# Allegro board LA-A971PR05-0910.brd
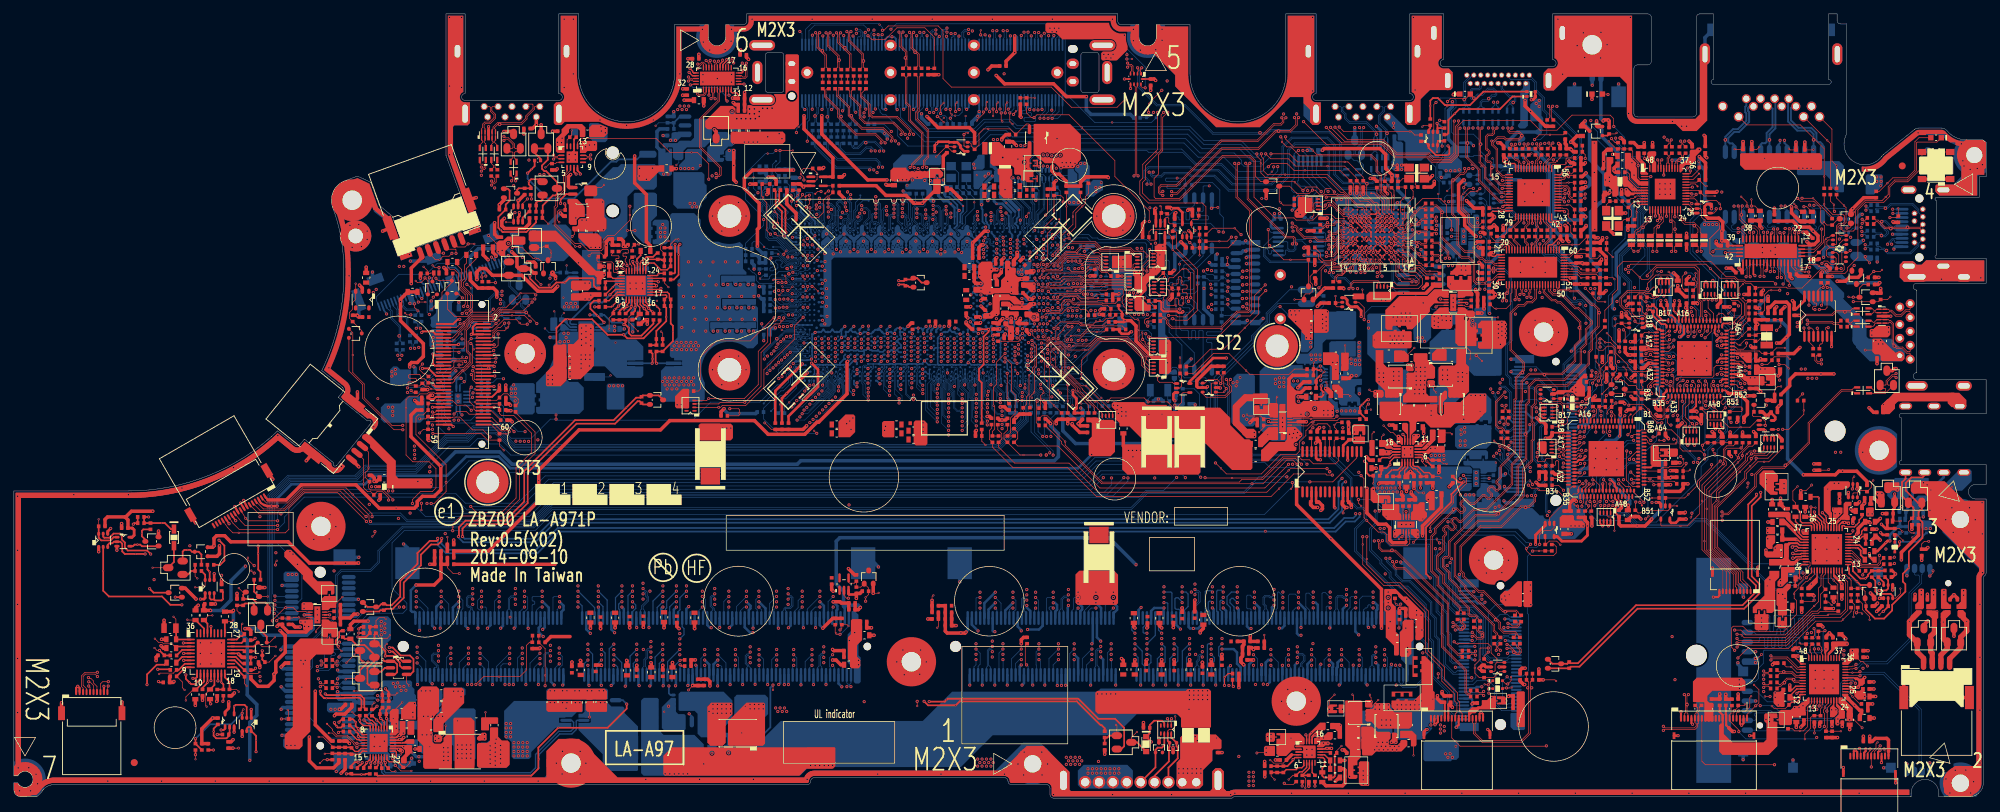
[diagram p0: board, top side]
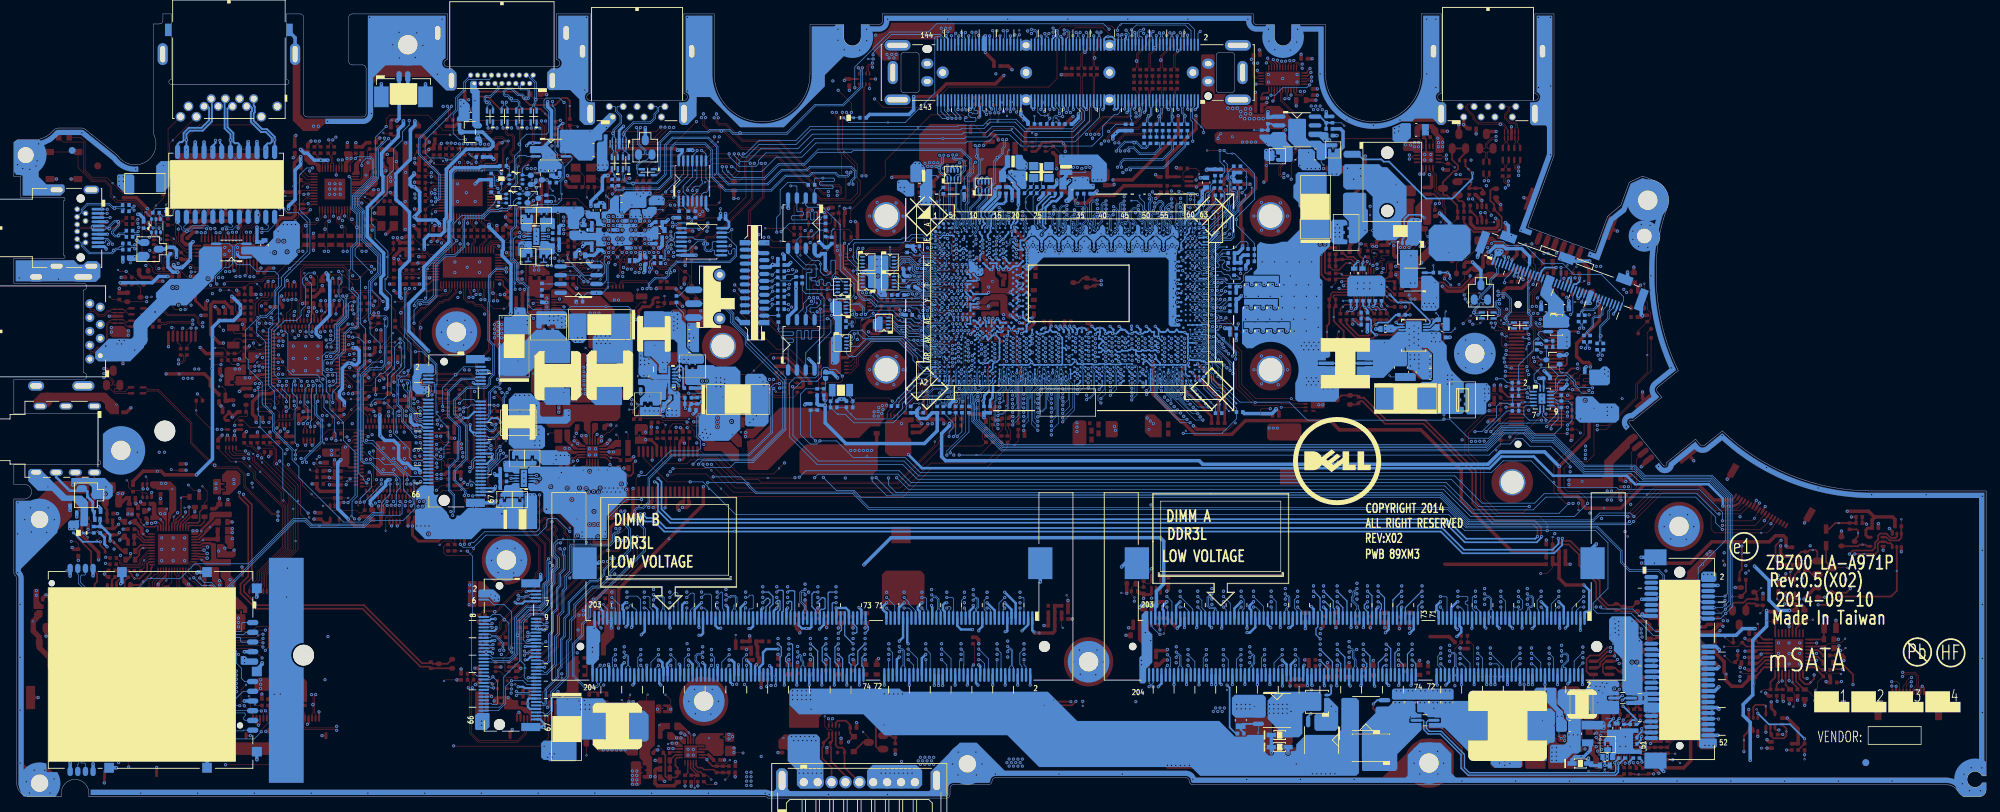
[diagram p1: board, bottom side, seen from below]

Outline 283.9 x 113 mm; copper layers: TOP, GND1, IN1, GND2, IN2, IN3, VCC, IN4, GND3, BOTTOM. Coordinates in mm from the lower left corner of the outline.

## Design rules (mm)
net group 18: nets H_THERMTRIP# H_THERMTRIP#_R
net group CPU_DPB_AUX_C: nets CPU_DPB_AUX#_C CPU_DPB_AUX_C
net group CPU_DPB_CTRL: nets CPU_DPB_CTRLCLK CPU_DPB_CTRLDAT
net group CPU_DPC_CTRL: nets CPU_DPC_CTRLCLK CPU_DPC_CTRLDAT
net group CRT-SYNC: nets HSYNC_DOCK VSYNC_DOCK
net group DDR_A_DQS0: nets DDR_A_DQS0 DDR_A_DQS#0
net group DDR_A_DQS2: nets DDR_A_DQS2 DDR_A_DQS#2
net group DDR_A_DQS4: nets DDR_A_DQS4 DDR_A_DQS#4
net group DDR_A_DQS6: nets DDR_A_DQS6 DDR_A_DQS#6
net group DDR_B_DQS0: nets DDR_B_DQS0 DDR_B_DQS#0
net group DDR_B_DQS2: nets DDR_B_DQS2 DDR_B_DQS#2
net group DDR_B_DQS4: nets DDR_B_DQS4 DDR_B_DQS#4
net group DDR_B_DQS6: nets DDR_B_DQS6 DDR_B_DQS#6
net group DDRA_CLK: nets M_CLK_DDR1 M_CLK_DDR#1
net group DDRB_CLK: nets M_CLK_DDR2 M_CLK_DDR#2
net group DIFFPAIR2: nets SW_MDP_AUX#_C SW_MDP_AUX_C
net group DP: nets CPU_DPB_AUX CPU_DPB_AUX#
net group M_CLK_DDR0: nets M_CLK_DDR0 M_CLK_DDR#0
net group M_CLK_DDR3: nets M_CLK_DDR3 M_CLK_DDR#3
net group REM_DIODE2_: nets REM_DIODE2_N REM_DIODE2_P
net group USB2.0: nets PS_USBP0_D+ PS_USBP0_D-
net group VMM_DPB_CTRL: nets VMM_DPB_CTRLCLK VMM_DPB_CTRLDAT
net group VMM_DPC_CTRL: nets VMM_DPC_CTRLCLK VMM_DPC_CTRLDAT
net group 10: nets INT_SPK_L+ INT_SPK_L- INT_SPK_R+ INT_SPK_R- INT_SPKR_L+ INT_SPKR_L- INT_SPKR_R+ INT_SPKR_R- VCCSENSE VSSSENSE
net group 12: nets H_CATERR# H_CPUPWRGD H_PROCHOT# H_PROCHOT#_R PCH_JTAG_TCK PCH_JTAG_TDI PCH_JTAG_TDO PCH_JTAG_TMS PCH_PLTRST# PCH_PLTRST#_EC PLTRST_LAN# PLTRST_MMI# PLTRST_USH# THERMATRIP2# THERMATRIP3# XDP_RST#_R
net group 12/12/15: nets BC_CLK_ECE1117 BC_CLK_ECE5048 BC_DAT_ECE1117 BC_DAT_ECE5048
net group 15: nets CHARGER_SMBCLK CHARGER_SMBDAT CLK_KBD CLK_MSE CLK_TP_SIO DAT_KBD DAT_MSE DAT_TP_SIO DDR_XDP_WAN_SMBCLK DDR_XDP_WAN_SMBDAT DMIC_CLK DMIC_CLK_L DOCK_SMB_CLK DOCK_SMB_DAT GPU_SMBCLK GPU_SMBDAT I2C1_SCL_VMM I2C1_SDA_VMM LAN_SMBCLK LAN_SMBDATA MEM_SMBCLK MEM_SMBDATA PBAT_SMBCLK PBAT_SMBDAT PCH_RTCRST# PCH_RTCX1 PCH_RTCX1_R PCH_RTCX2 SIO_SLP_A# SML0_SMBCLK SML0_SMBDATA SML1_SMBCLK SML1_SMBDATA SPI_CLK32 SPI_DIN32 SPI_DIN64 SPI_DO32 SPI_DO64 SPI_PCH_CS0#_R SPI_PCH_CS1#_R SPI_PCH_DO2_32 SPI_PCH_DO2_64 SPI_PCH_DO3_32 SPI_PCH_DO3_64 SRTCRST# SUSCLK SUSCLK_R USH_SMBCLK USH_SMBDAT XDP_DBRESET#
net group 20: nets CLK_PCI_DOCK CLK_PCI_LPDEBUG CLK_PCI_MEC CLK_PCI_SIO DOCK_LOM_TRD0+ DOCK_LOM_TRD0- DOCK_LOM_TRD1+ DOCK_LOM_TRD1- DOCK_LOM_TRD2+ DOCK_LOM_TRD2- DOCK_LOM_TRD3+ DOCK_LOM_TRD3- LAN_TX0+ LAN_TX0+L LAN_TX0- LAN_TX0-L LAN_TX1+ LAN_TX1+L LAN_TX1- LAN_TX1-L LAN_TX2+ LAN_TX2+L LAN_TX2- LAN_TX2-L LAN_TX3+ LAN_TX3+L LAN_TX3- LAN_TX3-L NB_LAN_TX0+ NB_LAN_TX0- NB_LAN_TX1+ NB_LAN_TX1- NB_LAN_TX2+ NB_LAN_TX2- NB_LAN_TX3+ NB_LAN_TX3- SPI_CLK64 SW_LAN_TX0+ SW_LAN_TX0- SW_LAN_TX1+ SW_LAN_TX1- SW_LAN_TX2+ SW_LAN_TX2- SW_LAN_TX3+ SW_LAN_TX3-
net group 20/15: nets CLK_PCIE_LAN CLK_PCIE_LAN# CLK_PCIE_MMI CLK_PCIE_MMI# CLK_PCIE_SATA CLK_PCIE_SATA# CLK_PCIE_WIGIG CLK_PCIE_WIGIG# CLK_PCIE_WLAN CLK_PCIE_WLAN# CPU_DPC_AUX CPU_DPC_AUX# DDI2_LANE_N0 DDI2_LANE_N1 DDI2_LANE_N2 DDI2_LANE_N3 DDI2_LANE_P0 DDI2_LANE_P1 DDI2_LANE_P2 DDI2_LANE_P3 DOCK_USBP0+ DOCK_USBP0- DOCK_USBP3+ DOCK_USBP3- DPB_DOCK_AUX DPB_DOCK_AUX# DPB_DOCK_LANE_N0 DPB_DOCK_LANE_N1 DPB_DOCK_LANE_N2 DPB_DOCK_LANE_N3 DPB_DOCK_LANE_P0 DPB_DOCK_LANE_P1 DPB_DOCK_LANE_P2 DPB_DOCK_LANE_P3 DPB_LANE_N0 DPB_LANE_N0_C DPB_LANE_N1 DPB_LANE_N1_C DPB_LANE_N2 DPB_LANE_N2_C DPB_LANE_N3 DPB_LANE_N3_C DPB_LANE_P0 DPB_LANE_P0_C DPB_LANE_P1 DPB_LANE_P1_C DPB_LANE_P2 DPB_LANE_P2_C DPB_LANE_P3 DPB_LANE_P3_C DPC_DOCK_AUX DPC_DOCK_AUX# DPC_DOCK_LANE_N0 DPC_DOCK_LANE_N1 DPC_DOCK_LANE_N2 DPC_DOCK_LANE_N3 DPC_DOCK_LANE_P0 DPC_DOCK_LANE_P1 DPC_DOCK_LANE_P2 DPC_DOCK_LANE_P3 DPC_LANE_N0 DPC_LANE_N0_C DPC_LANE_N1 DPC_LANE_N1_C DPC_LANE_N2 DPC_LANE_N2_C DPC_LANE_N3 DPC_LANE_N3_C DPC_LANE_P0 DPC_LANE_P0_C DPC_LANE_P1 DPC_LANE_P1_C DPC_LANE_P2 DPC_LANE_P2_C DPC_LANE_P3 DPC_LANE_P3_C EDP_CPU_AUX EDP_CPU_AUX# EDP_CPU_AUX#_C EDP_CPU_AUX_C EDP_CPU_LANE_N0 EDP_CPU_LANE_N0_C EDP_CPU_LANE_N1 EDP_CPU_LANE_N1_C EDP_CPU_LANE_P0 EDP_CPU_LANE_P0_C EDP_CPU_LANE_P1 EDP_CPU_LANE_P1_C HDMI_LANE_N0 HDMI_LANE_N1 HDMI_LANE_N2 HDMI_LANE_N3 HDMI_LANE_P0 HDMI_LANE_P1 HDMI_LANE_P2 HDMI_LANE_P3 MDP_AUX#_C MDP_AUX_C MDP_LANE_N0_C MDP_LANE_N1_C MDP_LANE_N2_C MDP_LANE_N3_C MDP_LANE_P0_C MDP_LANE_P1_C MDP_LANE_P2_C MDP_LANE_P3_C PCIE_PRX_GLANTX_N3 PCIE_PRX_GLANTX_N3_C PCIE_PRX_GLANTX_P3 PCIE_PRX_GLANTX_P3_C PCIE_PRX_MMITX_N1 PCIE_PRX_MMITX_N1_C PCIE_PRX_MMITX_P1 PCIE_PRX_MMITX_P1_C PCIE_PRX_SATATX_N6_L0 PCIE_PRX_SATATX_N6_L1 PCIE_PRX_SATATX_P6_L0 PCIE_PRX_SATATX_P6_L1 PCIE_PRX_WIGIGTX_N5 PCIE_PRX_WIGIGTX_P5 PCIE_PRX_WLANTX_N4 PCIE_PRX_WLANTX_P4 PCIE_PTX_GLANRX_N3 PCIE_PTX_GLANRX_N3_C PCIE_PTX_GLANRX_P3 PCIE_PTX_GLANRX_P3_C PCIE_PTX_MMIRX_N1 PCIE_PTX_MMIRX_N1_C PCIE_PTX_MMIRX_P1 PCIE_PTX_MMIRX_P1_C PCIE_PTX_SATARX_N6_L0 PCIE_PTX_SATARX_N6_L0_C PCIE_PTX_SATARX_N6_L1 PCIE_PTX_SATARX_N6_L1_C PCIE_PTX_SATARX_P6_L0 PCIE_PTX_SATARX_P6_L0_C PCIE_PTX_SATARX_P6_L1 PCIE_PTX_SATARX_P6_L1_C PCIE_PTX_WIGIGRX_N5 PCIE_PTX_WIGIGRX_N5_C PCIE_PTX_WIGIGRX_P5 PCIE_PTX_WIGIGRX_P5_C PCIE_PTX_WLANRX_N4 PCIE_PTX_WLANRX_N4_C PCIE_PTX_WLANRX_P4 PCIE_PTX_WLANRX_P4_C PS8338_AUX PS8338_AUX# PS8338_N0 PS8338_N0_C PS8338_N1 PS8338_N1_C PS8338_N2 PS8338_N2_C PS8338_N3 PS8338_N3_C PS8338_P0 PS8338_P0_C PS8338_P1 PS8338_P1_C PS8338_P2 PS8338_P2_C PS8338_P3 PS8338_P3_C SATA_PRX_DKTX_N0 SATA_PRX_DKTX_N0_C SATA_PRX_DKTX_P0 SATA_PRX_DKTX_P0_C SATA_PRX_DTX_N1 SATA_PRX_DTX_N1_C SATA_PRX_DTX_P1 SATA_PRX_DTX_P1_C SATA_PTX_DKRX_N0 SATA_PTX_DKRX_N0_C SATA_PTX_DKRX_P0 SATA_PTX_DKRX_P0_C SATA_PTX_DRX_N1 SATA_PTX_DRX_N1_C SATA_PTX_DRX_P1 SATA_PTX_DRX_P1_C SW_DPB_AUX SW_DPB_AUX# SW_DPB_AUX#_C SW_DPB_AUX_C SW_DPC_AUX SW_DPC_AUX# SW_DPC_AUX#_C SW_DPC_AUX_C SW_USBP3+ SW_USBP3- TMDS_CON_N0 TMDS_CON_N1 TMDS_CON_N2 TMDS_CON_P0 TMDS_CON_P1 TMDS_CON_P2 USB3RN1 USB3RN1_D- USB3RN2 USB3RN2_D- USB3RN4 USB3RN4_D- USB3RP1 USB3RP1_D+ USB3RP2 USB3RP2_D+ USB3RP4 USB3RP4_D+ USB3TN1 USB3TN1_D- USB3TN2 USB3TN2_C USB3TN2_D- USB3TN4 USB3TN4_C USB3TN4_D- USB3TP1 USB3TP1_D+ USB3TP2 USB3TP2_C USB3TP2_D+ USB3TP4 USB3TP4_C USB3TP4_D+ USBP0+ USBP0- USBP1+ USBP1- USBP1_R_D+ USBP1_R_D- USBP2+ USBP2- USBP3+ USBP3- USBP3_D+ USBP3_D- USBP4+ USBP4- USBP4_D+ USBP4_D- USBP5+ USBP5- USBP5_D+ USBP5_D- USBP6+ USBP6- USBP7+ USBP7- USBRBIAS VMM2320_AUX VMM2320_AUX# VMM2320_AUX#_C VMM2320_AUX_C VMM2320_N0 VMM2320_N0_C VMM2320_N1 VMM2320_N1_C VMM2320_N2 VMM2320_N2_C VMM2320_N3 VMM2320_N3_C VMM2320_P0 VMM2320_P0_C VMM2320_P1 VMM2320_P1_C VMM2320_P2 VMM2320_P2_C VMM2320_P3 VMM2320_P3_C WIGIG_AUX WIGIG_AUX# WIGIG_AUX#_C WIGIG_AUX_C WIGIG_LANE_N0 WIGIG_LANE_N0_C WIGIG_LANE_N1 WIGIG_LANE_N1_C WIGIG_LANE_N2 WIGIG_LANE_N2_C WIGIG_LANE_N3 WIGIG_LANE_N3_C WIGIG_LANE_P0 WIGIG_LANE_P0_C WIGIG_LANE_P1 WIGIG_LANE_P1_C WIGIG_LANE_P2 WIGIG_LANE_P2_C WIGIG_LANE_P3 WIGIG_LANE_P3_C
net group 24/20/18: nets SD_UHS2_D0N SD_UHS2_D0P SD_UHS2_D1N SD_UHS2_D1P
net group CRT-DAC: nets BLUE_DOCK GREEN_DOCK RED_DOCK
net group DDI1: nets DDI1_LANE_N0 DDI1_LANE_N0_C DDI1_LANE_N1 DDI1_LANE_N1_C DDI1_LANE_N2 DDI1_LANE_N2_C DDI1_LANE_N3 DDI1_LANE_N3_C DDI1_LANE_P0 DDI1_LANE_P0_C DDI1_LANE_P1 DDI1_LANE_P1_C DDI1_LANE_P2 DDI1_LANE_P2_C DDI1_LANE_P3 DDI1_LANE_P3_C
net group DDRA_CMD: nets DDR_A_BS0 DDR_A_BS1 DDR_A_BS2 DDR_A_CAS# DDR_A_MA0 DDR_A_MA1 DDR_A_MA2 DDR_A_MA3 DDR_A_MA4 DDR_A_MA5 DDR_A_MA6 DDR_A_MA7 DDR_A_MA8 DDR_A_MA9 DDR_A_MA10 DDR_A_MA11 DDR_A_MA12 DDR_A_MA13 DDR_A_MA14 DDR_A_MA15 DDR_A_RAS# DDR_A_WE#
net group DDRA_CTL: nets DDR_CKE0_DIMMA DDR_CKE1_DIMMA DDR_CS0_DIMMA# DDR_CS1_DIMMA# M_ODT0 M_ODT1
net group DDRA_D0: nets DDR_A_D0 DDR_A_D1 DDR_A_D2 DDR_A_D3 DDR_A_D4 DDR_A_D5 DDR_A_D6 DDR_A_D7
net group DDRA_D1: nets DDR_A_D8 DDR_A_D9 DDR_A_D10 DDR_A_D11 DDR_A_D12 DDR_A_D13 DDR_A_D14 DDR_A_D15
net group DDRA_D2: nets DDR_A_D16 DDR_A_D17 DDR_A_D18 DDR_A_D19 DDR_A_D20 DDR_A_D21 DDR_A_D22 DDR_A_D23
net group DDRA_D3: nets DDR_A_D24 DDR_A_D25 DDR_A_D26 DDR_A_D27 DDR_A_D28 DDR_A_D29 DDR_A_D30 DDR_A_D31
net group DDRA_D4: nets DDR_A_D32 DDR_A_D33 DDR_A_D34 DDR_A_D35 DDR_A_D36 DDR_A_D37 DDR_A_D38 DDR_A_D39
net group DDRA_D5: nets DDR_A_D40 DDR_A_D41 DDR_A_D42 DDR_A_D43 DDR_A_D44 DDR_A_D45 DDR_A_D46 DDR_A_D47
net group DDRA_D6: nets DDR_A_D48 DDR_A_D49 DDR_A_D50 DDR_A_D51 DDR_A_D52 DDR_A_D53 DDR_A_D54 DDR_A_D55
net group DDRA_D7: nets DDR_A_D56 DDR_A_D57 DDR_A_D58 DDR_A_D59 DDR_A_D60 DDR_A_D61 DDR_A_D62 DDR_A_D63
net group DDRA_DQS: nets DDR_A_DQS1 DDR_A_DQS3 DDR_A_DQS5 DDR_A_DQS7 DDR_A_DQS#1 DDR_A_DQS#3 DDR_A_DQS#5 DDR_A_DQS#7
net group DDRB_CMD: nets DDR_B_BS0 DDR_B_BS1 DDR_B_BS2 DDR_B_CAS# DDR_B_MA0 DDR_B_MA1 DDR_B_MA2 DDR_B_MA3 DDR_B_MA4 DDR_B_MA5 DDR_B_MA6 DDR_B_MA7 DDR_B_MA8 DDR_B_MA9 DDR_B_MA10 DDR_B_MA11 DDR_B_MA12 DDR_B_MA13 DDR_B_MA14 DDR_B_MA15 DDR_B_RAS# DDR_B_WE#
net group DDRB_CTL: nets DDR_CKE2_DIMMB DDR_CKE3_DIMMB DDR_CS2_DIMMB# DDR_CS3_DIMMB# M_ODT2 M_ODT3
net group DDRB_D0: nets DDR_B_D0 DDR_B_D1 DDR_B_D2 DDR_B_D3 DDR_B_D4 DDR_B_D5 DDR_B_D6 DDR_B_D7
net group DDRB_D1: nets DDR_B_D8 DDR_B_D9 DDR_B_D10 DDR_B_D11 DDR_B_D12 DDR_B_D13 DDR_B_D14 DDR_B_D15
net group DDRB_D2: nets DDR_B_D16 DDR_B_D17 DDR_B_D18 DDR_B_D19 DDR_B_D20 DDR_B_D21 DDR_B_D22 DDR_B_D23
net group DDRB_D3: nets DDR_B_D24 DDR_B_D25 DDR_B_D26 DDR_B_D27 DDR_B_D28 DDR_B_D29 DDR_B_D30 DDR_B_D31
net group DDRB_D4: nets DDR_B_D32 DDR_B_D33 DDR_B_D34 DDR_B_D35 DDR_B_D36 DDR_B_D37 DDR_B_D38 DDR_B_D39
net group DDRB_D5: nets DDR_B_D40 DDR_B_D41 DDR_B_D42 DDR_B_D43 DDR_B_D44 DDR_B_D45 DDR_B_D46 DDR_B_D47
net group DDRB_D6: nets DDR_B_D48 DDR_B_D49 DDR_B_D50 DDR_B_D51 DDR_B_D52 DDR_B_D53 DDR_B_D54 DDR_B_D55
net group DDRB_D7: nets DDR_B_D56 DDR_B_D57 DDR_B_D58 DDR_B_D59 DDR_B_D60 DDR_B_D61 DDR_B_D62 DDR_B_D63
net group DDRB_DQS: nets DDR_B_DQS1 DDR_B_DQS3 DDR_B_DQS5 DDR_B_DQS7 DDR_B_DQS#1 DDR_B_DQS#3 DDR_B_DQS#5 DDR_B_DQS#7
net group DMIC: nets DMIC0
net group HDA_8_15: nets PCH_AZ_BITCLK PCH_AZ_CODEC_BITCLK PCH_AZ_CODEC_RST# PCH_AZ_CODEC_SDIN0 PCH_AZ_CODEC_SDOUT PCH_AZ_CODEC_SYNC PCH_AZ_RST# PCH_AZ_SDIN0_R PCH_AZ_SDOUT PCH_AZ_SYNC
net group HDMI: nets HDMI_CLK_AUX HDMI_DAT_AUX# TMDS_CON_CLK TMDS_CON_CLK#
net group SD-CARD: nets SD/MMCCD# SD/MMCCLK SD/MMCCLK_R SD/MMCCMD SD/MMCDAT0 SD/MMCDAT1 SD/MMCDAT2 SD/MMCDAT2_R SD/MMCDAT3 SD/MMCDAT3_R SD_REXT SDWP
net group SPI: nets PCH_SPI_CLK PCH_SPI_CS0# PCH_SPI_CS1# PCH_SPI_DIN PCH_SPI_DO PCH_SPI_DO2 PCH_SPI_DO3 SPI_PCH_CLK SPI_PCH_CS0# SPI_PCH_CS1# SPI_PCH_DIN SPI_PCH_DO SPI_PCH_DO2 SPI_PCH_DO3
net group SVID: nets VIDALERT_N VIDSCLK VIDSOUT
net group THERMAL: nets REM_DIODE1_N REM_DIODE1_P REM_DIODE4_N REM_DIODE4_P
net group USB3.0: nets DOCK_USB3RN1 DOCK_USB3RP1 DOCK_USB3TN1 DOCK_USB3TP1 SW_USB3RN1 SW_USB3RP1 SW_USB3TN1 SW_USB3TP1 SW_USBP0+ SW_USBP0- USB3TN1_C USB3TP1_C USBP0_R_D+ USBP0_R_D-
nets with their own width: min track width 0.254; nets +3.3V_WWAN AUD_SENSE_A AUD_SENSE_B BAT1_LED# BAT1_LED#_Q BAT2_LED# BAT2_LED#_Q BATT_WHITE# BATT_YELLOW# CLK_BIASREF
nets with their own width: min track width 0.381; nets +PCH_RTC_VCCSUS3_3 +PCH_VCCDSW3_3 AUD_HP_OUT_L AUD_HP_OUT_L1 AUD_HP_OUT_R AUD_HP_OUT_R1 AUD_OUT_L AUD_OUT_R CFG_RCOMP PCH_OPI_COMP PCH_PCIE_RCOMP PROC_OPI_RCOMP SATA_COMP SM_RCOMP0 SM_RCOMP1 SM_RCOMP2 TDI_IREF
nets with their own width: min track width 0.508; nets +1.2V_LDO +1.05V_M +1.05V_MODPHY +1.05V_MODPHY_PCH +1.05V_MP +1.05V_RUN +1.5V_RUN_AUDIO +1.05V_RUN_UZ7 +1.05V_VCCST +1.05V_VMM_UV10 +1.05V_VMM_VDD +1.05V_VMM_VDDTX +1.8V_RUN_CARD +1.35V_MEM +1.35V_MEN_P +3.3V_ALW +3.3V_ALW2 +3.3V_ALW_PCH +3.3V_ALW_UE1 +3.3V_ALW_UE2 +3.3V_ALWP +3.3V_CAM +3.3V_LAN +3.3V_M +3.3V_M_TPM +3.3V_RTC_LDO +3.3V_RUN +3.3V_RUN_AUDIO +3.3V_RUN_UZ9 +3.3V_RUN_VDDA +3.3V_RUN_VDDIO +3.3V_SPI +3.3V_SUS +3.3V_TP +3.3V_VMM_UV10 +5V_ALW +5V_ALW2 +5V_ALWP +5V_RUN +5V_RUN_AUDIO +5V_RUN_UZ9 +AUX_LDO +CAP_LDO +COINCELL +DC_IN +DC_IN_SS +DCIN +DCIN_JACK +DCPRRTC +DIMM1_VREF_DQ +DIMM2_VREF_DQ +DOCK_PWR_BAR +GND_CHASSIS +LOM_VCT +MIC1_VREF_OUT +NBDOCK_DC_IN_SS +PBATT +PCH_ASATA3PLL +PCH_AUSB3PLL +PCH_VCC1P05 +PCH_VCCACLKPLL +PCH_VCCDSW +PCH_VCCDSW_R +RTC_CELL +RTC_CELL_VBAT +SIM_PWR +SM_VREF_CA +SM_VREF_CA_DIMM +SM_VREF_DQ0 +SM_VREF_DQ1 +V_DDR_REF +VCC_CORE +VCCIO_OUT +VCCIOA_OUT +VDDA_AVDD1 +VDDA_PVDD +VLDOIN_1.35V +VR_CAP +VREFOUT EDP_COMP GND GNDA N33048 N33050 N5261056
nets with their own width: min track width 1.016; nets +0.9V_LAN +1.5V_RUN +1.05V_RUN_VMM +3.3V_RUN_CARD +3.3V_RUN_VMM +3.3V_TSP +BL_PWR_SRC +VDISPLAY_VCC +VHDMI_VCC REGCTL_PNP10
nets with their own width: min track width 1.27; nets RING2 SLEEVE
nets with their own width: min track width 1.524; nets +0.675V_DDR_VTT +0.675V_P +3.3V_MMI +PWR_SRC
nets with their own width: min track width 2.032; nets +3.3V_HDD +3.3V_WLAN +5V_USB_CHG_PWR +LCDVDD +USB_RIGHT_PWR +USB_SIDE_PWR

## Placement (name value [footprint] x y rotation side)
C33  4.7U_0805_25V6-K  [C_0805]  106.62 97.01 270 top
C42  4.7P_0402_50V8C  [C_0402]  132.59 97.14 180 bottom
C43  4.7P_0402_50V8C  [C_0402]  137 97.14 0 bottom
C263  0.1U_0402_16V4Z  [C_0402]  267.14 8.17 180 top
C294  0.1U_0402_10V7K  [C_0402]  116.44 102.21 90 top
C295  0.1U_0402_10V7K  [C_0402]  115.86 95.25 270 bottom
C296  0.1U_0402_10V7K  [C_0402]  117.32 102.21 90 top
C297  0.1U_0402_10V7K  [C_0402]  116.75 95.25 270 bottom
C298  0.1U_0402_10V7K  [C_0402]  118.21 102.21 90 top
C299  0.1U_0402_10V7K  [C_0402]  117.64 95.25 270 bottom
C300  0.1U_0402_10V7K  [C_0402]  120.31 95.25 270 bottom
C301  0.1U_0402_10V7K  [C_0402]  121.2 95.25 270 bottom
C302  0.1U_0402_10V7K  [C_0402]  114.97 95.25 270 bottom
C303  0.1U_0402_10V7K  [C_0402]  119.1 102.21 90 top
C304  0.1U_0402_10V7K  [C_0402]  118.53 95.25 270 bottom
C305  0.1U_0402_10V7K  [C_0402]  119.99 102.21 90 top
C306  0.1U_0402_10V7K  [C_0402]  119.42 95.25 270 bottom
C307  0.1U_0402_10V7K  [C_0402]  120.88 102.21 90 top
C308  0.1U_0402_10V7K  [C_0402]  121.77 102.21 90 top
C309  0.1U_0402_10V7K  [C_0402]  122.66 102.21 90 top
C310  0.033U_0402_16V7K  [C_0402]  122.98 97.09 270 bottom
C311  0.033U_0402_16V7K  [C_0402]  131.6 105.16 270 top
C312  0.01U_0402_16V7K  [C_0402]  127.99 104.24 90 top
C313  0.01U_0402_16V7K  [C_0402]  128.88 104.24 90 top
C314  0.01U_0402_16V7K  [C_0402]  129.77 105.16 270 top
C315  0.01U_0402_16V7K  [C_0402]  130.66 105.16 270 top
C316  1U_0402_6.3V6K  [C_0402]  142.83 105.49 180 top
C317  0.1U_0603_50V7K  [C_0603]  103.8 96.89 270 top
C318  0.1U_0603_50V7K  [C_0603]  105.07 96.89 270 top
C319  4.7P_0402_50V8C  [C_0402]  144.87 100.9 270 top
CA1  680P_0402_50V7K  [C_0402]  273.94 41.19 0 bottom
CA2  220P_0402_50V7K  [C_0402]  272.34 41.24 180 bottom
CA3  220P_0402_50V7K  [C_0402]  270.51 41 180 top
CA4  680P_0402_50V7K  [C_0402]  267.32 43.26 180 top
CA5  100P_0402_50V8J  [C_0402]  67.42 74.41 270 top
CA6  100P_0402_50V8J  [C_0402]  68.31 74.41 270 top
CA7  0.1U_0402_25V6  [C_0402]  66.61 75.6 180 top
CA8  0.1U_0402_25V6  [C_0402]  263.94 40.33 0 top
CA9  10U_0603_6.3V6M  [C_0603]  263.73 41.38 0 top
CA10  4.7U_0603_6.3V6K  [C_0603]  254.62 27.72 0 top
CA11  0.1U_0402_25V6  [C_0402]  258.31 30.21 270 top
CA12  680P_0402_50V7K  [C_0402]  275.81 43.1 270 bottom
CA13  680P_0402_50V7K  [C_0402]  269.09 55.59 180 top
CA16  4.7U_0603_6.3V6K  [C_0603]  254.56 37.38 180 top
CA17  0.1U_0402_25V6  [C_0402]  255.38 40.79 90 top
CA18  4.7U_0603_6.3V6K  [C_0603]  254.31 40.93 90 top
CA19  1000P_0402_50V7K  [C_0402]  277.8 28.6 0 top
CA22  1000P_0402_50V7K  [C_0402]  274.52 28.6 180 top
CA23  1000P_0402_50V7K  [C_0402]  276.36 28.6 180 top
CA24  1000P_0402_50V7K  [C_0402]  280.68 28.6 180 top
CA25  10U_0603_6.3V6M  [C_0603]  258.62 43.41 180 top
CA26  1U_0603_10V4Z  [C_0603]  266.5 39.81 0 top
CA27  0.1U_0402_25V6  [C_0402]  264.47 29.3 90 top
CA28  0.1U_0402_25V6  [C_0402]  265.42 29.3 90 top
CA29  1U_0603_10V6K  [C_0603]  256.46 41.95 270 top
CA30  22P_0402_50V8J  [C_0402]  257.35 28.31 270 top
CA31  1U_0603_10V6K  [C_0603]  256.46 31.66 180 top
CA33  15P_0402_50V8J  [C_0402]  260.78 28.24 270 top
CA35  2.2U_0402_6.3V6M  [C_0402]  266.04 41.76 270 top
CA41  0.1U_0402_25V6  [C_0402]  274.18 40.31 270 top
CA43  4.7U_0603_6.3V6K  [C_0603]  266.45 34.35 0 top
CA44  4.7U_0603_6.3V6K  [C_0603]  266.42 35.58 0 top
CA45  0.1U_0402_25V6  [C_0402]  255.96 33.83 270 top
CA46  10U_0603_6.3V6M  [C_0603]  255.13 35.22 180 top
CA47  0.1U_0402_25V6  [C_0402]  255.21 36.3 180 top
CA48  10U_0603_6.3V6M  [C_0603]  254.88 34.14 270 top
CA49  1U_0603_10V6K  [C_0603]  257.86 41.95 270 top
CA50  0.1U_0402_25V6  [C_0402]  263.13 30.21 270 top
CA51  4.7U_0603_6.3V6K  [C_0603]  266.57 37.69 0 top
CA52  4.7U_0603_6.3V6K  [C_0603]  254.56 39.79 180 top
CA53  4.7U_0603_6.3V6K  [C_0603]  261.93 30.33 270 top
CC1  12P_0402_50V8J  [C_0402]  164.05 57.19 180 bottom
CC2  12P_0402_50V8J  [C_0402]  165.42 57.19 0 bottom
CC3  1U_0402_6.3V6K  [C_0402]  169.22 56.82 270 bottom
CC4  1U_0402_6.3V6K  [C_0402]  167.31 58.06 90 bottom
CC5  27P_0402_50V8J  [C_0402]  149.21 55.52 90 bottom
CC6  0.1U_0402_25V6  [C_0402]  167.12 78.45 90 bottom
CC7  0.1U_0402_25V6  [C_0402]  173.93 77.7 180 bottom
CC8  15P_0402_50V8J  [C_0402]  135.74 87.16 0 bottom
CC9  33P_0402_50V8J  [C_0402]  166.74 72.58 0 top
CC10  33P_0402_50V8J  [C_0402]  166.17 79.91 90 bottom
CC11  15P_0402_50V8J  [C_0402]  138.43 88.05 180 bottom
CC12  33P_0402_50V8J  [C_0402]  140.72 54.74 270 top
CC13  33P_0402_50V8J  [C_0402]  141.63 54.72 270 top
CC14  33P_0402_50V8J  [C_0402]  143.01 54.72 270 top
CC15  33P_0402_50V8J  [C_0402]  143.97 54.15 270 top
CC17  0.1U_0402_25V6  [C_0402]  63.69 60.49 180 bottom
CC18  0.1U_0402_25V6  [C_0402]  69.89 58.78 0 top
CC19  0.1U_0402_25V6  [C_0402]  59.63 57.73 180 top
CC20  22P_0402_50V8J  [C_0402]  105.34 77.35 0 bottom
CC21  0.1U_0402_25V6  [C_0402]  69.9 56.81 0 top
CC22  0.1U_0402_25V6  [C_0402]  59.63 56.87 180 top
CC23  22U_0603_6.3V6M  [C_0603]  137.08 73.19 270 top
CC24  100P_0402_50V8J  [C_0402]  117.89 87.29 0 top
CC25  2.2U_0402_6.3V6M  [C_0402]  129.02 54.02 0 top
CC26  2.2U_0402_6.3V6M  [C_0402]  131.75 68.69 0 top
CC27  2.2U_0402_6.3V6M  [C_0402]  129.35 67.53 90 top
CC28  2.2U_0402_6.3V6M  [C_0402]  135.59 68.66 180 top
CC29  10U_0603_6.3V6M  [C_0603]  128.78 52.94 0 top
CC30  10U_0603_6.3V6M  [C_0603]  128.78 51.67 0 top
CC31  10U_0603_6.3V6M  [C_0603]  127.76 53.83 180 top
CC32  10U_0603_6.3V6M  [C_0603]  127.76 52.56 180 top
CC33  10U_0603_6.3V6M  [C_0603]  117.73 53.83 0 top
CC34  10U_0603_6.3V6M  [C_0603]  117.73 52.56 0 top
CC35  0.1U_0402_25V6  [C_0402]  117.89 89.51 0 top
CC36  22U_0603_6.3V6M  [C_0603]  132.91 87.74 0 top
CC37  1U_0402_6.3V6K  [C_0402]  137.08 69.87 90 top
CC39  330U_D3_2.5VY_R6M  [C_D2]  182.89 57.44 180 bottom
CC40  1U_0402_6.3V6K  [C_0402]  145.54 76.8 135 top
CC41  330U_D3_2.5VY_R6M  [C_D3]  169.28 54.55 270 top
CC42  330U_D3_2.5VY_R6M  [C_D3]  164.52 54.55 270 top
CC43  1U_0402_6.3V6K  [C_0402]  146.71 86.78 180 top
CC44  1U_0402_6.3V6K  [C_0402]  146.71 87.67 180 top
CC47  22U_0603_6.3V6M  [C_0603]  139.7 86.91 0 top
CC48  0.1U_0402_10V7K  [C_0402]  143.58 67.62 90 top
CC49  0.1U_0402_10V7K  [C_0402]  142.74 68.37 180 top
CC50  1U_0402_6.3V6K  [C_0402]  143.46 66.24 180 top
CC51  22U_0603_6.3V6M  [C_0603]  139.7 88.12 0 top
CC52  0.1U_0402_10V7K  [C_0402]  145.78 69.81 90 top
CC53  1U_0402_6.3V6K  [C_0402]  145.8 75.81 270 top
CC54  0.1U_0402_10V7K  [C_0402]  145.25 72.81 180 top
CC55  22U_0603_6.3V6M  [C_0603]  143.4 88.18 0 top
CC56  22U_0603_6.3V6M  [C_0603]  143.4 86.91 0 top
CC57  0.1U_0402_10V7K  [C_0402]  139.83 69.37 90 top
CC58  1U_0402_6.3V6K  [C_0402]  138.5 68.42 90 top
CC59  1U_0402_6.3V6K  [C_0402]  142.18 77 0 top
CC60  10U_0603_6.3V6M  [C_0603]  159.71 53.96 270 top
CC61  1U_0402_6.3V6K  [C_0402]  144.32 69.81 90 top
CC62  22U_0603_6.3V6M  [C_0603]  142.61 69.82 90 top
CC63  22U_0603_6.3V6M  [C_0603]  141.4 71.67 90 top
CC64  22U_0603_6.3V6M  [C_0603]  141.49 74.14 180 top
CC65  1U_0402_6.3V6K  [C_0402]  139.33 52.18 180 top
CC66  0.1U_0402_10V7K  [C_0402]  141.25 75.29 180 top
CC67  100U_1206_6.3V6M  [C_1206]  152.21 87.61 0 bottom
CC68  1U_0402_6.3V6K  [C_0402]  139.81 71.97 90 top
CC69  1U_0402_6.3V6K  [C_0402]  145.25 74.02 180 top
CC70  1U_0402_6.3V6K  [C_0402]  138.5 74.16 270 top
CC71  1U_0402_6.3V6K  [C_0402]  143.94 76.95 270 top
CC72  1U_0402_6.3V6K  [C_0402]  140.97 67.58 90 top
CC73  1U_0402_6.3V6K  [C_0402]  144.45 67.59 90 top
CC77  100U_1206_6.3V6M  [C_1206]  132.89 88.56 180 bottom
CC78  1U_0402_6.3V6K  [C_0402]  141.32 77 180 top
CC79  22U_0603_6.3V6M  [C_0603]  138.25 75.24 180 top
CC80  1U_0402_6.3V6K  [C_0402]  145.78 67.46 90 top
CC81  100U_1206_6.3V6M  [C_1206]  141.59 89.57 180 bottom
CC82  1U_0402_6.3V6K  [C_0402]  139.29 87.16 0 bottom
CC83  100P_0402_50V8J  [C_0402]  112.13 87.59 90 top
CC84  22U_0603_6.3V6M  [C_0603]  138.24 76.5 180 top
CC85  22U_0603_6.3V6M  [C_0603]  126.69 89.71 270 top
CC97  0.47U_0402_10V6K  [C_0402]  138 67.56 0 top
CC100  1U_0402_6.3V6K  [C_0402]  156.86 69.63 0 top
CC101  0.1U_0402_16V4Z  [C_0402]  143.26 56.84 270 top
CC102  0.1U_0402_16V4Z  [C_0402]  114.99 90.73 0 top
CC103  0.1U_0402_16V4Z  [C_0402]  170.56 83.92 180 top
CC104  0.1U_0402_16V4Z  [C_0402]  169.63 79.29 180 top
CC105  0.1U_0402_16V4Z  [C_0402]  167.09 82.52 90 top
CC106  0.1U_0402_16V4Z  [C_0402]  163.39 80.83 180 top
CC107  0.1U_0402_16V4Z  [C_0402]  155.11 73.69 180 bottom
CC108  0.1U_0402_25V6  [C_0402]  154.57 69.62 0 bottom
CC109  0.1U_0402_16V4Z  [C_0402]  107.91 55.63 180 bottom
CC110  0.1U_0402_16V4Z  [C_0402]  123.04 29.82 180 top
CC111  0.1U_0402_16V4Z  [C_0402]  69.9 57.71 0 top
CC112  0.1U_0402_16V4Z  [C_0402]  58.79 59.78 270 top
CD1  0.1U_0402_25V6  [C_0402]  61.47 33.7 180 top
CD2  1U_0402_6.3V6K  [C_0402]  95.43 26.22 270 top
CD3  1U_0402_6.3V6K  [C_0402]  90.61 26.22 270 top
CD4  1U_0402_6.3V6K  [C_0402]  88.64 26.15 270 top
CD5  2.2U_0402_6.3V6M  [C_0402]  61.47 34.65 180 top
CD6  0.1U_0402_25V6  [C_0402]  74.62 22.46 270 top
CD7  1U_0402_6.3V6K  [C_0402]  84.45 26.09 270 top
CD8  1U_0402_6.3V6K  [C_0402]  93.4 17.55 90 top
CD9  1U_0402_6.3V6K  [C_0402]  89.65 17.55 90 top
CD10  1U_0402_6.3V6K  [C_0402]  83.75 18.25 90 top
CD11  1U_0402_6.3V6K  [C_0402]  80.32 18.06 90 top
CD12  10U_0603_6.3V6M  [C_0603]  97.97 26.71 270 top
CD13  10U_0603_6.3V6M  [C_0603]  93.59 26.77 270 top
CD14  10U_0603_6.3V6M  [C_0603]  86.54 26.71 270 top
CD15  10U_0603_6.3V6M  [C_0603]  82.99 26.71 270 top
CD16  10U_0603_6.3V6M  [C_0603]  94.8 17.44 90 top
CD17  10U_0603_6.3V6M  [C_0603]  91.75 17.44 90 top
CD18  10U_0603_6.3V6M  [C_0603]  88.26 17.69 90 top
CD19  10U_0603_6.3V6M  [C_0603]  81.59 17.76 90 top
CD20  330U_D3_2.5VY_R6M  [C_D3]  100.25 46.37 90 top
CD21  0.022U_0402_16V7K  [C_0402]  63.31 35.6 180 top
CD22  0.1U_0402_25V6  [C_0402]  99.37 16.22 90 top
CD23  2.2U_0402_6.3V6M  [C_0402]  98.48 16.22 90 top
CD24  0.1U_0402_25V6  [C_0402]  120.4 20.3 180 top
CD25  0.1U_0402_25V6  [C_0402]  120.4 21.25 180 top
CD26  0.1U_0402_25V6  [C_0402]  121.85 25.43 0 top
CD27  0.1U_0402_25V6  [C_0402]  121.85 24.54 0 top
CD28  10U_0603_6.3V6M  [C_0603]  120.9 19.22 180 top
CD29  10U_0603_6.3V6M  [C_0603]  121.74 23.46 0 top
CD30  0.1U_0402_25V6  [C_0402]  117.72 31.74 270 top
CD31  2.2U_0402_6.3V6M  [C_0402]  121.1 28.11 180 top
CD32  0.1U_0402_25V6  [C_0402]  121.1 27.15 180 top
CD33  2.2U_0402_6.3V6M  [C_0402]  134.07 24.86 0 top
CD34  0.1U_0402_25V6  [C_0402]  134.07 25.81 0 top
CD35  0.1U_0402_25V6  [C_0402]  145.85 22.25 90 top
CD36  0.022U_0402_16V7K  [C_0402]  179.08 22.58 0 top
CD37  1U_0402_6.3V6K  [C_0402]  169.98 25.93 90 top
CD38  1U_0402_6.3V6K  [C_0402]  166.9 26.22 270 top
CD39  1U_0402_6.3V6K  [C_0402]  163.18 26.15 270 top
CD40  1U_0402_6.3V6K  [C_0402]  168.17 25.87 90 top
CD41  1U_0402_6.3V6K  [C_0402]  173.89 19.14 90 top
CD42  1U_0402_6.3V6K  [C_0402]  171.09 18 90 top
CD43  1U_0402_6.3V6K  [C_0402]  167.03 18.38 90 top
CD44  1U_0402_6.3V6K  [C_0402]  162.99 18.38 90 top
CD45  10U_0603_6.3V6M  [C_0603]  159.69 17.82 90 top
CD46  10U_0603_6.3V6M  [C_0603]  171.22 26.39 270 top
CD47  10U_0603_6.3V6M  [C_0603]  164.9 26.64 270 top
CD48  10U_0603_6.3V6M  [C_0603]  161.21 26.64 270 top
CD49  10U_0603_6.3V6M  [C_0603]  172.36 17.82 90 top
CD50  10U_0603_6.3V6M  [C_0603]  169.25 17.82 90 top
CD51  10U_0603_6.3V6M  [C_0603]  165.21 17.82 90 top
CD52  10U_0603_6.3V6M  [C_0603]  161.34 17.82 90 top
CD53  330U_D3_2.5VY_R6M  [C_D3]  156.2 37.91 270 top
CD54  0.022U_0402_16V7K  [C_0402]  132.17 26.77 0 top
CD55  0.1U_0402_25V6  [C_0402]  176.86 20.8 0 top
CD56  2.2U_0402_6.3V6M  [C_0402]  176.61 19.92 0 top
CD57  0.1U_0402_25V6  [C_0402]  199.87 20.93 180 top
CD58  0.1U_0402_25V6  [C_0402]  199.87 21.88 180 top
CD59  0.1U_0402_25V6  [C_0402]  201.12 23.15 0 top
CD60  0.1U_0402_25V6  [C_0402]  201.12 24.11 0 top
CD61  10U_0603_6.3V6M  [C_0603]  199.86 22.96 180 top
CD62  10U_0603_6.3V6M  [C_0603]  201.13 25.19 0 top
CD63  2.2U_0402_6.3V6M  [C_0402]  200.35 27.22 0 top
CD64  0.1U_0402_25V6  [C_0402]  200.35 26.27 0 top
CE1  10U_0603_6.3V6M  [C_0603]  239 49.73 270 top
CE2  0.1U_0402_25V6  [C_0402]  236.83 48.08 0 top
CE3  0.1U_0402_25V6  [C_0402]  231.25 56.13 90 top
CE4  0.1U_0402_10V7K  [C_0402]  221.42 52.62 180 top
CE5  0.1U_0402_25V6  [C_0402]  221.42 46.93 180 top
CE6  0.1U_0402_25V6  [C_0402]  231.06 40.57 90 top
CE7  4.7U_0603_6.3V6K  [C_0603]  232.33 41.47 270 top
CE8  0.047U_0402_16V4Z  [C_0402]  236.83 45.16 0 top
CE9  33P_0402_50V8J  [C_0402]  219.57 47.9 270 top
CE10  1U_0402_6.3V6K  [C_0402]  250.68 73.51 180 top
CE11  0.1U_0402_25V6  [C_0402]  252.51 69.84 270 top
CE12  1U_0402_6.3V6K  [C_0402]  249.78 71.66 90 top
CE13  0.1U_0402_25V6  [C_0402]  240.77 71.34 90 top
CE14  1U_0402_6.3V6K  [C_0402]  234.3 61.96 180 top
CE15  1U_0402_6.3V6K  [C_0402]  249.83 63.04 0 top
CE16  0.1U_0402_25V6  [C_0402]  250.74 59.94 270 top
CE17  0.1U_0402_25V6  [C_0402]  246.15 70.78 180 top
CE18  0.1U_0402_25V6  [C_0402]  249.85 59.94 270 top
CE19  0.1U_0402_25V6  [C_0402]  241.44 55.75 270 top
CE20  0.1U_0402_25V6  [C_0402]  249.83 63.93 0 top
CE21  10U_0603_6.3V6M  [C_0603]  252.83 61.64 0 top
CE22  0.1U_0402_25V6  [C_0402]  237.02 55.94 270 top
CE23  0.1U_0402_25V6  [C_0402]  234.3 64.82 180 top
CE24  2200P_0402_50V7K  [C_0402]  239.83 71.04 180 top
CE25  0.1U_0402_25V6  [C_0402]  249.05 54.84 180 top
CE26  2200P_0402_50V7K  [C_0402]  237.07 71.04 0 top
CE27  2200P_0402_50V7K  [C_0402]  235.94 71.05 270 top
CE28  22P_0402_50V8J  [C_0402]  250.69 65.84 270 top
CE29  22P_0402_50V8J  [C_0402]  250.74 66.71 90 top
CE30  1U_0402_6.3V6K  [C_0402]  243.81 51.21 90 top
CE31  4.7U_0603_6.3V6K  [C_0603]  239.51 74.56 270 top
CE32  10U_0603_6.3V6M  [C_0603]  54.03 46.08 180 top
CE34  4.7P_0402_50V8C  [C_0402]  232.09 61.06 180 top
CE35  100P_0402_50V8J  [C_0402]  128.34 73.82 90 top
CE36  0.1U_0402_25V6  [C_0402]  234.3 57.49 90 top
CE37  100P_0402_50V8J  [C_0402]  53.25 27.99 270 top
CE38  0.1U_0402_25V6  [C_0402]  234.3 66.66 180 top
CE39  100P_0402_50V8J  [C_0402]  90.35 56.92 90 top
CE40  4700P_0402_25V7K  [C_0402]  241.72 72.26 270 top
CE41  0.1U_0402_25V6  [C_0402]  51.82 43.7 0 top
CE42  0.1U_0402_25V6  [C_0402]  51.19 45.59 90 top
CE44  1U_0402_6.3V6K  [C_0402]  251.56 69.84 270 top
CE45  1U_0402_6.3V6K  [C_0402]  249.77 68.94 0 top
CE46  100P_0402_50V8J  [C_0402]  223.89 18.71 90 top
CI1  100U_1206_6.3V6M  [C_1206]  80.72 96.3 0 bottom
CI3  0.1U_0402_25V6  [C_0402]  74.32 96.48 180 top
CI4  0.1U_0402_10V7K  [C_0402]  68.71 90.55 270 top
CI5  0.1U_0402_10V7K  [C_0402]  69.6 90.55 270 top
CI6  10U_0603_6.3V6M  [C_0603]  247.83 78.97 90 bottom
CI7  0.1U_0402_25V6  [C_0402]  248.91 79.21 90 bottom
CI8  100U_1206_6.3V6M  [C_1206]  201.79 93.38 180 bottom
CI10  0.1U_0402_25V6  [C_0402]  199.64 95.29 180 bottom
CI11  10U_0603_6.3V6M  [C_0603]  206.41 91.1 270 bottom
CI12  0.1U_0402_25V6  [C_0402]  205.33 91.05 270 bottom
CI13  0.1U_0402_10V7K  [C_0402]  263.91 67.92 180 top
CI14  100U_1206_6.3V6M  [C_1206]  268.66 64.55 90 top
CI16  0.1U_0402_10V7K  [C_0402]  263.91 68.81 180 top
CI17  0.1U_0402_25V6K~D  [C_0402]  269.11 63.41 180 top
CI19  0.1U_0402_25V6  [C_0402]  79.2 96.09 180 top
CI20  10U_0603_6.3V6M  [C_0603]  81.85 95.73 0 top
CI27  0.1U_0402_10V7K  [C_0402]  197.78 89.15 270 bottom
CI28  0.1U_0402_10V7K  [C_0402]  196.89 89.15 270 bottom
CI38  0.1U_0402_25V6  [C_0402]  163.64 103.62 270 top
CI414  0.1U_0402_25V6  [C_0402]  105.18 99.02 180 top
CI415  0.1U_0402_25V6  [C_0402]  105.18 100.81 180 top
CI416  0.1U_0402_25V6  [C_0402]  105.18 99.92 180 top
CI417  0.1U_0402_25V6  [C_0402]  98.6 106.54 180 top
CI418  0.1U_0402_25V6  [C_0402]  96.91 102.2 270 top
CI419  0.1U_0402_25V6  [C_0402]  104.53 107.1 0 top
CI420  4.7U_0603_6.3V6K  [C_0603]  97.9 100.57 0 top
CL1  0.1U_0402_10V7K  [C_0402]  240.64 92.93 90 top
CL2  0.1U_0402_10V7K  [C_0402]  239.75 92.93 90 top
CL3  0.1U_0402_10V7K  [C_0402]  229.68 90.72 180 top
CL4  10U_0603_6.3V6M  [C_0603]  230.43 87.1 180 top
CL5  0.1U_0402_10V7K  [C_0402]  238.67 93.85 270 top
CL6  0.1U_0402_10V7K  [C_0402]  237.78 93.85 270 top
CL7  1U_0603_10V6K  [C_0603]  232.23 91.29 180 top
CL8  0.1U_0402_10V7K  [C_0402]  235.89 92.93 90 top
CL9  0.1U_0402_10V7K  [C_0402]  241.59 92.93 90 top
CL10  0.1U_0402_10V7K  [C_0402]  232.35 87.03 180 top
CL11  0.1U_0402_10V7K  [C_0402]  240.78 80.76 270 top
CL12  22U_0603_6.3V6M  [C_0603]  229.73 92.05 90 top
CL13  27P_0402_50V8J  [C_0402]  228.83 86.02 0 top
CL14  27P_0402_50V8J  [C_0402]  232.33 82.45 90 top
CL15  0.1U_0402_10V7K  [C_0402]  258.93 79.77 90 top
CL16  0.47U_0603_10V7K  [C_0603]  258.81 84.49 270 top
CL17  0.47U_0603_10V7K  [C_0603]  257.54 84.49 270 top
CL18  470P_0402_50V7K  [C_0402]  243.47 93.9 270 top
CL19  0.1U_0402_10V7K  [C_0402]  255.68 75.48 0 top
CL20  0.47U_0603_10V7K  [C_0603]  251.32 84.62 270 top
CL21  0.47U_0603_10V7K  [C_0603]  250.05 84.62 270 top
CL22  150P_1808_2.5KV8J  [C_1808]  267.21 88.56 180 bottom
CL23  0.1U_0402_10V7K  [C_0402]  201.73 42.08 90 top
CL24  470P_0402_50V7K  [C_0402]  200.85 42.08 90 top
CL25  0.1U_0402_25V6  [C_0402]  248.79 75.73 180 top
CL26  0.1U_0402_25V6  [C_0402]  246.68 79.61 180 top
CL27  0.1U_0402_25V6  [C_0402]  253.42 83.15 90 top
CMOS1  SHORT PADS~D  [SHORTPADS]  167.06 60.93 270 bottom
CN1  0.1U_0402_25V6  [C_0402]  47.73 13.47 0 top
CN2  0.1U_0402_25V6  [C_0402]  40.45 19.47 180 top
CN3  .01U_0402_16V7K  [C_0402]  45.85 19.91 180 top
CN4  .01U_0402_16V7K  [C_0402]  45.85 19.02 180 top
CN5  .01U_0402_16V7K  [C_0402]  45.85 16.74 180 top
CN6  .01U_0402_16V7K  [C_0402]  45.85 15.85 180 top
CR1  4.7U_0603_6.3V6K  [C_0603]  265.72 14.65 0 top
CR2  0.1U_0402_25V6  [C_0402]  255.64 15.6 180 top
CR3  0.1U_0402_25V6  [C_0402]  266.15 15.73 0 top
CR4  0.1U_0402_25V6  [C_0402]  260.9 22.19 90 top
CR6  0.1U_0402_25V6  [C_0402]  263.2 11.86 270 top
CR7  4.7U_0603_6.3V6K  [C_0603]  256.58 10.97 90 top
CR8  0.1U_0402_25V6  [C_0402]  257.67 11.26 90 top
CR9  4.7U_0603_6.3V6K  [C_0603]  262.93 23.6 270 top
CR10  0.1U_0402_25V6  [C_0402]  261.85 23.11 270 top
CR13  0.1U_0402_25V6  [C_0402]  266.19 21.25 180 top
CR14  4.7U_0603_6.3V6K  [C_0603]  267.12 11.54 180 top
CR15  0.1U_0402_25V6  [C_0402]  266.88 12.62 180 top
CR17  1U_0402_6.3V6K  [C_0402]  254.61 13.44 0 top
CR18  4.7U_0603_6.3V6K  [C_0603]  254.24 14.52 0 top
CR19  0.1U_0402_25V6  [C_0402]  266.19 20.29 180 top
CR21  0.1U_0402_25V6  [C_0402]  256.13 21.39 270 top
CR22  0.1U_0402_25V6  [C_0402]  267.07 16.75 180 top
CR23  5P_0402_50V8C  [C_0402]  259.75 24.04 90 top
CR24  0.1U_0402_10V7K  [C_0402]  252.88 17.57 0 top
CR25  0.1U_0402_10V7K  [C_0402]  252.88 18.46 0 top
CR26  0.1U_0402_10V7K  [C_0402]  252.88 16.68 0 top
CR27  0.1U_0402_10V7K  [C_0402]  252.88 15.79 0 top
CR31  1U_0402_6.3V6K  [C_0402]  261.72 11.93 270 top
CR34  4.7U_0603_6.3V6K  [C_0603]  264.26 11.98 270 top
CR35  0.1U_0402_25V6  [C_0402]  260.85 9.64 270 top
CV1  0.1U_0402_10V7K  [C_0402]  58.66 68.67 90 bottom
CV2  0.1U_0402_10V7K  [C_0402]  57.77 68.67 90 bottom
CV3  0.1U_0402_10V7K  [C_0402]  57.9 65.75 90 bottom
CV4  0.1U_0402_10V7K  [C_0402]  57.01 65.75 90 bottom
CV5  0.1U_0402_10V7K  [C_0402]  55.99 64.6 90 bottom
CV6  0.1U_0402_10V7K  [C_0402]  55.11 64.6 90 bottom
CV7  0.1U_0603_50V7K  [C_0603]  61.46 70.59 180 bottom
CV8  0.1U_0402_25V6  [C_0402]  56.87 61.38 0 bottom
CV9  10U_0603_6.3V6M  [C_0603]  50.71 74.28 90 top
CV10  0.01U_0402_16V7K  [C_0402]  51.11 69.32 180 top
CV11  1000P_0402_50V7K  [C_0402]  61.46 65.89 0 bottom
CV12  0.1U_0603_50V7K  [C_0603]  62.66 70.59 0 bottom
CV24  0.1U_0402_16V4Z  [C_0402]  219.76 97.04 90 bottom
CV27  10U_0603_6.3V6M  [C_0603]  217.42 98.3 0 bottom
CV30  0.1U_0402_10V7K  [C_0402]  217.67 99.44 0 bottom
CV60  2.2U_0402_6.3V6M  [C_0402]  224.67 92.24 0 top
CV61  0.01U_0402_16V7K  [C_0402]  214.45 92.68 90 top
CV62  0.01U_0402_16V7K  [C_0402]  212.36 84.06 180 top
CV66  0.1U_0402_25V6  [C_0402]  222.64 81.83 0 top
CV69  0.1U_0402_25V6  [C_0402]  224.66 91.36 0 top
CV71  0.1U_0402_25V6  [C_0402]  221.68 93.59 270 top
CV72  0.1U_0402_25V6  [C_0402]  220.8 93.59 270 top
CV73  0.1U_0402_25V6  [C_0402]  219.91 93.59 270 top
CV74  0.1U_0402_25V6  [C_0402]  219.02 93.59 270 top
CV75  0.1U_0402_25V6  [C_0402]  218.06 93.59 270 top
CV76  0.1U_0402_25V6  [C_0402]  217.18 93.59 270 top
CV77  0.1U_0402_25V6  [C_0402]  216.22 93.59 270 top
CV78  0.1U_0402_25V6  [C_0402]  215.33 93.59 270 top
CV79  0.1U_0402_25V6  [C_0402]  225.58 86.91 180 top
CV80  0.1U_0402_25V6  [C_0402]  225.58 86.02 180 top
CV82  10U_0603_6.3V6M  [C_0603]  191.64 81.87 180 bottom
CV83  0.1U_0402_25V6  [C_0402]  191.49 80.79 180 bottom
CV84  0.1U_0402_25V6  [C_0402]  195.69 82.3 90 bottom
CV85  0.01U_0402_16V7K  [C_0402]  195.69 80.23 270 bottom
CV86  0.01U_0402_16V7K  [C_0402]  199.78 81.87 0 bottom
CV87  1U_0603_10V6K  [C_0603]  201.89 81.17 90 bottom
CV88  0.1U_0402_25V6  [C_0402]  197.64 80.97 90 bottom
CV89  0.01U_0402_16V7K  [C_0402]  199.81 79.92 0 bottom
CV90  10U_0603_6.3V6M  [C_0603]  199.99 83.97 90 bottom
CV91  0.1U_0402_25V6  [C_0402]  191.49 79.9 180 bottom
CV92  0.01U_0402_16V7K  [C_0402]  194.08 84.53 90 bottom
CV93  0.01U_0402_16V7K  [C_0402]  199.78 82.89 0 bottom
CV94  10U_0603_6.3V6M  [C_0603]  201.66 78.21 0 bottom
CV95  0.1U_0402_25V6  [C_0402]  192.96 77.9 270 bottom
CV96  0.01U_0402_16V7K  [C_0402]  193.15 84.54 90 bottom
CV97  0.01U_0402_16V7K  [C_0402]  199.81 78.97 0 bottom
CV98  0.01U_0402_16V7K  [C_0402]  191.49 83.02 180 bottom
CV99  0.01U_0402_16V7K  [C_0402]  197.23 85.19 180 bottom
CV100  0.1U_0402_25V6  [C_0402]  198.91 84.21 90 bottom
CV101  10U_0603_6.3V6M  [C_0603]  197.16 86.33 180 bottom
CV102  0.1U_0402_10V7K  [C_0402]  204.13 83.91 180 top
CV103  0.1U_0402_10V7K  [C_0402]  204.13 83.02 180 top
CV104  0.1U_0402_10V7K  [C_0402]  204.13 82.13 180 top
CV105  0.1U_0402_10V7K  [C_0402]  204.13 81.24 180 top
CV106  0.1U_0402_10V7K  [C_0402]  204.13 80.35 180 top
CV107  0.1U_0402_10V7K  [C_0402]  204.13 79.46 180 top
CV108  0.1U_0402_10V7K  [C_0402]  204.13 78.57 180 top
CV109  0.1U_0402_10V7K  [C_0402]  204.13 77.68 180 top
CV110  0.1U_0402_10V7K  [C_0402]  204.13 85.68 180 top
CV111  0.1U_0402_10V7K  [C_0402]  204.13 84.79 180 top
CV113  18P_0402_50V8J  [C_0402]  199.14 89.68 90 top
CV114  0.1U_0402_25V6  [C_0402]  207.89 72.38 270 bottom
CV115  22P_0402_50V8J  [C_0402]  202.1 88.05 0 top
CV116  470P_0402_50V7K  [C_0402]  206.33 81.42 180 bottom
CV117  470P_0402_50V7K  [C_0402]  206.33 80.53 180 bottom
CV118  0.1U_0402_10V7K  [C_0402]  205.4 79.6 0 bottom
CV119  0.1U_0402_10V7K  [C_0402]  186.8 84.57 270 bottom
CV120  0.1U_0402_10V7K  [C_0402]  185.79 84.57 270 bottom
CV121  0.1U_0402_25V6  [C_0402]  181.46 83.48 0 bottom
CV122  0.1U_0402_10V7K  [C_0402]  190.79 77.98 0 bottom
CV123  0.1U_0402_10V7K  [C_0402]  190.79 77.09 0 bottom
CV124  0.1U_0402_25V6  [C_0402]  187.71 93.38 180 bottom
CV145  0.1U_0402_25V6  [C_0402]  207.82 26.66 270 top
CV146  0.1U_0402_25V6  [C_0402]  208.71 26.66 270 top
CV147  0.1U_0402_25V6  [C_0402]  210.17 25.51 270 top
CV148  0.1U_0402_25V6  [C_0402]  211.06 25.51 270 top
CV149  0.1U_0402_25V6  [C_0402]  216.97 26.34 270 top
CV150  0.1U_0402_25V6  [C_0402]  216.08 26.34 270 top
CV152  0.1U_0402_25V6  [C_0402]  213.09 23.16 270 top
CV153  0.1U_0402_25V6  [C_0402]  213.98 23.16 270 top
CV156  0.1U_0402_25V6  [C_0402]  215.9 23.16 270 top
CV157  0.1U_0402_25V6  [C_0402]  216.79 23.16 270 top
CV501  0.1U_0402_10V7K  [C_0402]  267.72 81.76 180 bottom
CV502  0.1U_0402_10V7K  [C_0402]  267.72 80.87 180 bottom
CV503  0.1U_0402_10V7K  [C_0402]  268.22 79.03 180 bottom
CV504  0.1U_0402_10V7K  [C_0402]  268.22 79.92 180 bottom
CV505  0.1U_0402_10V7K  [C_0402]  267.72 83.6 180 top
CV506  0.1U_0402_10V7K  [C_0402]  267.72 82.71 180 top
CV507  0.1U_0402_10V7K  [C_0402]  268.24 84.57 180 bottom
CV508  0.1U_0402_10V7K  [C_0402]  268.24 85.46 180 bottom
CV509  .01U_0402_16V7K  [C_0402]  267.31 77.89 0 bottom
CV510  0.1U_0402_16V4Z  [C_0402]  261.35 79.36 270 bottom
CV511  0.1U_0402_25V6  [C_0402]  256.27 70.47 270 top
CV512  0.1U_0402_10V7K  [C_0402]  259 64.76 270 top
CV513  0.1U_0402_10V7K  [C_0402]  259.89 64.76 270 top
CV518  0.1U_0402_10V7K  [C_0402]  206.31 82.33 180 bottom
CV600  0.1U_0402_25V6  [C_0402]  222.64 80.94 0 top
CV601  0.1U_0402_25V6  [C_0402]  212.38 78.33 180 top
CV602  0.1U_0402_25V6  [C_0402]  212.5 72.11 180 top
CV603  0.01U_0402_16V7K  [C_0402]  224.68 74.07 90 top
CV604  0.01U_0402_16V7K  [C_0402]  224.87 77.11 90 top
CV605  2.2U_0402_6.3V6M  [C_0402]  212.64 81.34 180 top
CV606  0.1U_0402_25V6  [C_0402]  221.63 81.84 270 top
CV607  0.1U_0402_25V6  [C_0402]  220.75 81.84 270 top
CV608  0.1U_0402_25V6  [C_0402]  219.86 81.84 270 top
CV609  0.1U_0402_25V6  [C_0402]  218.97 81.84 270 top
CV610  0.1U_0402_25V6  [C_0402]  218.08 81.84 270 top
CV611  0.1U_0402_25V6  [C_0402]  217.19 81.84 270 top
CV612  0.1U_0402_25V6  [C_0402]  216.3 81.84 270 top
CV613  0.1U_0402_25V6  [C_0402]  215.41 81.84 270 top
CZ1  0.1U_0402_25V6  [C_0402]  75.11 75.65 90 top
CZ2  0.1U_0402_16V4Z  [C_0402]  70.16 79.91 90 top
CZ4  0.1U_0402_25V6  [C_0402]  186.66 42.65 0 top
CZ5  4700P_0402_25V7K  [C_0402]  191.24 42.65 0 top
CZ6  2200P_0402_50V7K  [C_0402]  187.62 51.85 90 top
CZ7  2200P_0402_50V7K  [C_0402]  192.2 51.65 90 top
CZ9  0.1U_0402_25V6  [C_0402]  191.17 54.14 0 top
CZ10  0.1U_0402_25V6  [C_0402]  246.43 13.35 90 top
CZ11  0.1U_0402_25V6  [C_0402]  245.55 13.36 90 top
CZ12  0.1U_0402_25V6  [C_0402]  244.37 13.36 90 top
CZ13  0.1U_0402_10V7K  [C_0402]  208.49 21.24 0 top
CZ14  0.1U_0402_10V7K  [C_0402]  208.49 20.35 0 top
CZ15  0.1U_0402_25V6  [C_0402]  216.73 12.95 180 top
CZ16  0.047U_0402_16V4Z  [C_0402]  216.73 14.73 180 top
CZ17  0.1U_0402_25V6  [C_0402]  215.81 13.84 0 top
CZ18  0.1U_0402_25V6  [C_0402]  217.68 30.01 180 top
CZ19  4.7U_0603_6.3V6K  [C_0603]  216.52 28.93 0 top
CZ20  0.047U_0402_16V4Z  [C_0402]  216.76 27.85 0 top
CZ21  0.1U_0402_10V7K  [C_0402]  209.7 15.52 0 top
CZ22  0.1U_0402_10V7K  [C_0402]  209.7 14.63 0 top
CZ23  470P_0402_50V7K  [C_0402]  212.98 46.52 0 bottom
CZ24  0.1U_0402_10V7K  [C_0402]  212.98 44.68 0 bottom
CZ25  220P_0402_50V7K  [C_0402]  144.21 95.61 180 top
CZ27  0.1U_0402_25V6  [C_0402]  211.57 13.7 180 top
CZ28  0.1U_0402_25V6  [C_0402]  206.81 13.82 90 top
CZ29  0.1U_0402_25V6  [C_0402]  205.92 13.82 90 top
CZ30  10P_0402_50V8J  [C_0402]  218.61 17.93 0 top
CZ31  10P_0402_50V8J  [C_0402]  217.74 17.93 180 top
CZ32  0.1U_0402_10V7K  [C_0402]  215.19 55.74 270 top
CZ33  0.1U_0402_10V7K  [C_0402]  214.3 55.74 270 top
CZ34  0.1U_0402_25V6  [C_0402]  252.95 55.61 0 top
CZ35  0.01U_0402_16V7K  [C_0402]  253.45 57.2 0 top
CZ36  0.1U_0402_10V7K  [C_0402]  199.07 42.08 90 top
CZ37  470P_0402_50V7K  [C_0402]  199.96 42.08 90 top
CZ38  10U_0603_6.3V6M  [C_0603]  143.12 93.19 90 top
CZ39  0.1U_0402_10V7K  [C_0402]  182.63 51.92 180 top
CZ40  0.1U_0402_10V7K  [C_0402]  46.08 27.86 0 top
CZ41  470P_0402_50V7K  [C_0402]  46.08 26.91 0 top
CZ42  470P_0402_50V7K  [C_0402]  46.08 25.96 0 top
CZ43  0.1U_0402_10V7K  [C_0402]  46.08 25.01 0 top
CZ44  0.1U_0402_10V7K  [C_0402]  209.78 72.62 0 top
CZ45  470P_0402_50V7K  [C_0402]  209.78 71.73 0 top
CZ46  1000P_0402_50V7K  [C_0402]  209.78 70.84 0 top
CZ47  0.1U_0402_10V7K  [C_0402]  209.78 69.89 0 top
CZ48  0.1U_0402_25V6  [C_0402]  239.76 40.19 90 top
CZ49  470P_0402_50V7K  [C_0402]  212.98 45.63 0 bottom
CZ50  0.1U_0402_10V7K  [C_0402]  212.98 47.41 0 bottom
CZ51  0.047U_0402_16V4Z  [C_0402]  224.14 40.44 90 top
CZ52  0.047U_0402_16V4Z  [C_0402]  225.86 58.19 0 top
CZ53  33P_0402_50V8J  [C_0402]  225.86 59.08 0 top
CZ54  22U_0603_6.3V6M  [C_0603]  223.19 39.47 270 top
CZ55  33P_0402_50V8J  [C_0402]  223.19 40.44 90 top
CZ56  0.1U_0402_10V7K  [C_0402]  181.71 56.43 0 top
CZ57  150U_B2_6.3VM_R35M  [C_B2]  212.06 40.17 0 bottom
CZ58  0.1U_0402_10V7K  [C_0402]  215 52.76 270 top
CZ59  0.1U_0402_10V7K  [C_0402]  214.11 52.76 270 top
CZ60  470P_0402_50V7K  [C_0402]  179.9 54.58 180 top
CZ62  470P_0402_50V7K  [C_0402]  179.9 53.7 180 top
CZ63  33P_0402_50V8J  [C_0402]  229.27 61.95 0 top
CZ64  33P_0402_50V8J  [C_0402]  229.9 64.3 270 top
CZ65  33P_0402_50V8J  [C_0402]  227.75 63.59 0 top
CZ66  47P_0402_50V8J  [C_0402]  216.76 30.9 0 top
CZ68  0.047U_0402_16V4Z  [C_0402]  247.31 13.33 90 top
D19  -  [RB751S40T1G_SOD523-2]  164.43 98.03 180 bottom
D20  -  [L30ESD24VC3-2_SOT23-3]  101.08 95.07 0 top
DA1  AZ5123-02S.R7G_SOT23-3  [AZ5123-02SPR7G_SOT23-3]  272.02 43.64 90 bottom
DA2  -  [L03ESDL5V0CC3-2_SOT23-3]  273.67 44.64 180 top
DA3  AZ5123-02S.R7G_SOT23-3  [AZ5123-02SPR7G_SOT23-3]  269.77 44.74 180 top
DA4  -  [RB751S40T1G_SOD523-2]  270.75 36.87 270 top
DA5  -  [RB751S40T1G_SOD523-2]  273.91 38.21 0 bottom
DA6  -  [L03ESDL5V0CC3-2_SOT23-3]  274.96 24.5 180 top
DA7  -  [L03ESDL5V0CC3-2_SOT23-3]  279.27 24.5 180 top
DE1  -  [RB751S40T1G_SOD523-2]  54.03 44.87 180 top
DI1  -  [L05ESDL5V0NA-4_SLP2510P8-10-9]  67.33 95.11 180 top
DI2  -  [AZC199-02SPR7G_SOT23-3]  71.93 95.69 180 top
DI3  -  [AZC199-02SPR7G_SOT23-3]  193.01 94.81 0 bottom
DI4  -  [L05ESDL5V0NA-4_SLP2510P8-10-9]  268.47 70.44 90 top
DI5  -  [AZC199-02SPR7G_SOT23-3]  269.61 61.59 180 top
DI6  -  [L05ESDL5V0NA-4_SLP2510P8-10-9]  195.76 94.72 180 bottom
DV1  -  [BAT54CW_SOT323-3]  60.25 74.43 0 top
DV2  -  [BAT54CW_SOT323-3]  63.04 74.56 0 top
DV3  -  [BAT54CW_SOT323-3]  50.07 66.97 270 top
DV4  -  [AZC199-02SPR7G_SOT23-3]  72.72 73.91 0 bottom
DZ1  -  [RB751S40T1G_SOD523-2]  212.88 15.78 0 top
DZ2  -  [RB751S40T1G_SOD523-2]  212.88 16.92 0 top
DZ3  -  [RB751S40T1G_SOD523-2]  214.13 85.85 90 bottom
DZ4  -  [RB751S40T1G_SOD523-2]  213.73 89.96 270 bottom
DZ5  -  [RB751S40T1G_SOD523-2]  223.63 57.51 0 top
DZ6  -  [RB751S40T1G_SOD523-2]  223.63 56.4 0 top
FD1  FIDUCIAL MARK~D  [FIDUCIAL_C40M80]  17.32 5.12 180 bottom
FD2  FIDUCIAL MARK~D  [FIDUCIAL_C40M80]  17.32 5.12 0 top
FD3  FIDUCIAL MARK~D  [FIDUCIAL_C40M80]  275.51 93.32 180 bottom
FD4  FIDUCIAL MARK~D  [FIDUCIAL_C40M80]  271.83 91.1 0 top
H1  -  [H_2P3]  282.2 92.65 0 top
H2  -  [H_2P5]  280.2 40.15 0 top
H3  -  [H_2P5]  280.2 2.15 0 top
H4  -  [H_2P8]  220.2 67.15 0 top
H5  -  [H_2P8]  213 34.3 0 top
H6  -  [H_2P8]  184.6 13.97 0 top
H7  -  [H_2P5]  146.65 4.94 0 top
H8  -  [H_2P8]  129.2 19.65 0 top
H9  -  [H_2P8]  80.2 5.05 0 top
H10  -  [H_2P8]  44.2 39.15 0 top
H11  -  [H_2P8]  268.5 50.1 0 top
H12  -  [H_2P8]  48.7 86.15 0 top
H13  -  [H_3P4]  158.32 83.87 0 top
H14  -  [H_3P4]  158.32 61.73 0 top
H15  -  [H_3P4]  103 83.87 0 top
H16  -  [H_3P4]  103 61.73 0 top
H17  -  [H_2P8]  73.6 64.05 0 top
H18  -  [H_2P8]  227.2 108.55 0 top
H19  -  [H_2P1]  49.2 81 0 top
H20  -  [H_3P0N]  242.2 20.6 0 top
H21  -  [H_3P0N]  262.17 52.9 0 top
JAPS1  ACES_50506-01841-P01  [ACES_50506-01841-P01_18P-NPM]  36.12 43.51 210 top
JDEG1  ACES_50521-01041-P01  [ACES_50521-01041-P01_10P]  250 29.78 180 top
JDIMM1  LCN_DAN06-K4406-0103  [LCN_DAN06-K4406-0103_204P]  57.8 25.95 180 bottom
JDIMM2  LCN_DAN06-K4406-0103  [LCN_DAN06-K4406-0103_204P]  137.3 25.95 180 bottom
JDOCK1  JAE_WD2F144WB8R500-DT  [JAE_WD2F144WB8R500-DT_144P]  113.45 100.55 0 bottom
JEDP1  ACES_50398-04041-001  [ACES_50398-04041-001_40P]  70.89 77.46 200 bottom
JFAN1  ACES_50277-0040N-001  [ACES_50277-0040N-001_4P]  50.96 51.7 231.1 top
JHDMI1  LCN_AUF05-1922S10-0019  [LCN_AUF05-1922S10-0019_19P]  209.15 104.17 0 bottom
JHP1  SINGA_2SJ3080-003111F  [SINGA_2SJ3080-003111F_6P]  272.3 56.48 90 bottom
JKBTP1  CONCR_205160FW010  [CONCR_205160FW010_16P]  203.98 11.5 0 top
JLED1  ACES_50277-0060N-001  [ACES_50277-0060N-001_6P-T]  64.44 80.62 199.8 top
JLOM1  SANTA_130456-511  [SANTA_130456-511_13P-T]  249.38 100.78 0 bottom
JLPDE1  HB_A531015-SCHR21  [HB_A531015-SCHR21_10P]  8.96 15.28 0 top
JMDP1  ACON_MAR2E-20K1800  [ACON_MAR2E-20K1800_20P]  274.79 84.86 90 bottom
JMINI3  LCN_DAN08-52406-0500  [LCN_DAN08-52406-0500_52P]  48.2 31.85 270 bottom
JNGFF1  BELLW_80148-3521  [BELLW_80148-3521_67P-T]  208.72 29.85 270 bottom
JNGFF2  BELLW_80149-3221  [BELLW_80149-3221_67P]  216.69 62.15 270 bottom
JRTC1  TYCO_2-1775293-2~D  [TYCO_2-1775293-2_2P]  228.45 103.95 0 bottom
JSD1  T-SOL_156-2000302608_NR  [T-SOL_156-2000302608_19P_NR-S]  249.53 23.9 270 bottom
JSH1  CONCR_205120FW010  [CONCR_205120FW010_12P]  264.35 6.05 0 top
JSPI1  E-T_6700K-Y20N-00L  [E-T_6700K-Y20N-00L_20P]  175.88 69.52 270 bottom
JSPK1  ACES_50279-0040N-001  [ACES_50279-0040N-001_4P]  274.9 19.42 0 top
JTAG1  @SHORT PADS~D  [SHORTPADS]  245.91 51.67 90 top
JUSB1  SANTA_373070-2  [SANTA_373070-2_9P]  75.2 98.14 0 bottom
JUSB2  SANTA_373070-2  [SANTA_373070-2_9P]  197.69 98.14 0 bottom
JUSB3  TAITW_PUBAUE-09FLBS1FF4H0  [TAITW_PUBAUE-09FLBS1FF4H0_9P-T]  271.47 63.75 270 bottom
JUSH1  CONCR_205200FW010  [CONCR_205200FW010_20P]  239.98 11.5 0 top
JXDP1  SAMTE_BSH-030-01-L-D-A  [SAMTE_BSH-030-01-L-D-A_60P]  61.85 68.32 270 top
LA2  BLM15BD601SN1D_2P  [MURAT_BLM15BD601SN1D_2P]  269.68 39.92 0 top
LA3  BLM15BD601SN1D_2P  [MURAT_BLM15BD601SN1D_2P]  271.49 40.17 0 bottom
LA5  BLM15PX600SN1D_2P  [MURAT_BLM15PX600SN1D_2P]  264.23 42.39 0 top
LA6  BLM15PX330SN1D_2P  [MURAT_BLM15PX330SN1D_2P]  274.19 27.55 270 top
LA7  BLM15PX330SN1D_2P  [MURAT_BLM15PX330SN1D_2P]  275.72 27.55 270 top
LA8  BLM15PX330SN1D_2P  [MURAT_BLM15PX330SN1D_2P]  278.32 27.55 270 top
LA9  BLM15PX330SN1D_2P  [MURAT_BLM15PX330SN1D_2P]  280.23 27.55 270 top
LA10  BLM15PX330SN1D_2P  [MURAT_BLM15PX330SN1D_2P]  267.3 41.62 90 top
LA11  BLM15PX330SN1D_2P  [MURAT_BLM15PX330SN1D_2P]  274.81 39.64 180 bottom
LC1  2.2UH_LQM2MPN2R2NG0L_30%  [MURAT_LQM2MPN2R2NG0L_2P]  141.38 93.64 180 top
LC2  2.2UH_LQM2MPN2R2NG0L_30%  [MURAT_LQM2MPN2R2NG0L_2P]  142.67 91.77 270 top
LC3  2.2UH_LQM2MPN2R2NG0L_30%  [MURAT_LQM2MPN2R2NG0L_2P]  153.76 89.7 180 bottom
LC4  2.2UH_LQM2MPN2R2NG0L_30%  [MURAT_LQM2MPN2R2NG0L_2P]  132.45 91.77 270 bottom
LC5  2.2UH_LQM2MPN2R2NG0L_30%  [MURAT_LQM2MPN2R2NG0L_2P]  139.27 91.73 0 bottom
LED3  LTW-193ZDS5_WHITE  [LED_LTW-193ZDS5_2P]  277.45 95.15 180 top
LED5  LTW-193ZDS5_WHITE  [LED_LTW-193ZDS5_2P]  227.17 101.45 0 top
LED6  LTW-193ZDS5_WHITE  [LED_LTW-193ZDS5_2P]  208.14 101.45 0 top
LED7  LTW-295DSKS-5A_YEL-WHITE  [LED_LTW-295DSKS-5A_4P]  217.8 101.1 0 top
LI1  DLW21HN900HQ2L_4P  [MURAT_DLW21HN900HQ2L_4P]  67.93 91.97 90 top
LI2  DLW21HN900HQ2L_4P  [MURAT_DLW21HN900HQ2L_4P]  69.58 91.97 90 top
LI3  DLW21HN900HQ2L_4P  [MURAT_DLW21HN900HQ2L_4P]  72.36 89.99 90 top
LI4  DLW21HN900HQ2L_4P  [MURAT_DLW21HN900HQ2L_4P]  191.8 90.62 0 bottom
LI5  DLW21HN900HQ2L_4P  [MURAT_DLW21HN900HQ2L_4P]  265.27 67.94 0 top
LI6  DLW21HN900HQ2L_4P  [MURAT_DLW21HN900HQ2L_4P]  265.27 69.72 0 top
LI7  DLW21HN900HQ2L_4P  [MURAT_DLW21HN900HQ2L_4P]  265.34 58.33 0 top
LI8  DLW21HN900HQ2L_4P  [MURAT_DLW21HN900HQ2L_4P]  196.97 90.64 90 bottom
LI9  DLW21HN900HQ2L_4P  [MURAT_DLW21HN900HQ2L_4P]  195.38 90.64 90 bottom
LL1  4.7UH_BRC2012T4R7MD_20%  [TAIYO_BRC2012T4R7MD_2P]  231.99 88.82 180 top
LL21  12NH_0603CS-120EJTS_5%  [DELTA_0603CS-120EJTS_2P]  232.84 81.01 270 top
LL22  12NH_0603CS-120EJTS_5%  [DELTA_0603CS-120EJTS_2P]  234.2 81.01 270 top
LL23  12NH_0603CS-120EJTS_5%  [DELTA_0603CS-120EJTS_2P]  235.56 81.01 270 top
LL24  12NH_0603CS-120EJTS_5%  [DELTA_0603CS-120EJTS_2P]  236.92 81.01 270 top
LL25  12NH_0603CS-120EJTS_5%  [DELTA_0603CS-120EJTS_2P]  238.29 81.01 270 top
LL26  12NH_0603CS-120EJTS_5%  [DELTA_0603CS-120EJTS_2P]  239.65 81.01 270 top
LL27  12NH_0603CS-120EJTS_5%  [DELTA_0603CS-120EJTS_2P]  241.9 81.01 270 top
LL28  12NH_0603CS-120EJTS_5%  [DELTA_0603CS-120EJTS_2P]  243.28 81.01 270 top
LV1  BLM15BB221SN1D_2P~D  [MURAT_BLM15BB221SN1D_2P]  61.2 75.67 180 top
LV3  DLW21HN900HQ2L_4P  [MURAT_DLW21HN900HQ2L_4P]  214.94 97.37 90 bottom
LV6  DLW21HN900HQ2L_4P  [MURAT_DLW21HN900HQ2L_4P]  208.65 97.37 90 bottom
LV10  DLW21HN900HQ2L_4P  [MURAT_DLW21HN900HQ2L_4P]  210.75 97.37 90 bottom
LV12  DLW21HN900HQ2L_4P  [MURAT_DLW21HN900HQ2L_4P]  212.85 97.37 90 bottom
LV22  BLM15PX181SN1D_2P  [MURAT_BLM15PX181SN1D_2P]  203.05 82.25 270 bottom
LV23  BLM15PX181SN1D_2P  [MURAT_BLM15PX181SN1D_2P]  202.1 84.24 180 bottom
LV24  BLM15PX181SN1D_2P  [MURAT_BLM15PX181SN1D_2P]  192 85.69 270 bottom
LV25  BLM15PX181SN1D_2P  [MURAT_BLM15PX181SN1D_2P]  194.52 77.44 0 bottom
LV27  DLW21HN900HQ2L_4P  [MURAT_DLW21HN900HQ2L_4P]  72.59 69.12 180 bottom
LZ1  DLW21HN900HQ2L_4P  [MURAT_DLW21HN900HQ2L_4P]  67.97 67.67 180 bottom
NOREF  -  []  102.54 35.72 0 top
NOREF#2  -  []  280.2 2.15 0 top
NOREF#3  -  []  118.1 -49.87 0 top
NOREF#4  -  []  213 34.3 0 top
NOREF#5  -  []  68.21 45.52 0 top
NOREF#6  -  []  220.2 67.15 0 top
NOREF#7  -  []  184.6 13.97 0 top
NOREF#8  -  []  181.85 65.15 0 top
NOREF#9  -  []  158.32 83.87 0 top
NOREF#10  -  []  158.32 61.73 0 top
NOREF#11  -  []  62.47 45 0 top
NOREF#12  -  []  86.22 6.13 0 top
NOREF#13  -  []  44.2 39.15 0 top
NOREF#14  -  []  280.2 40.15 0 top
NOREF#15  -  []  268.5 50.1 0 top
NOREF#16  -  []  73.6 64.05 0 top
NOREF#17  -  []  80.2 5.05 0 top
NOREF#18  -  []  159.72 39.72 0 top
NOREF#19  -  []  48.7 86.15 0 top
NOREF#20  -  []  76.31 42.04 0 top
NOREF#21  -  []  49.2 81 0 top
NOREF#22  -  []  282.2 92.65 0 top
NOREF#23  -  []  110.8 11.04 0 top
